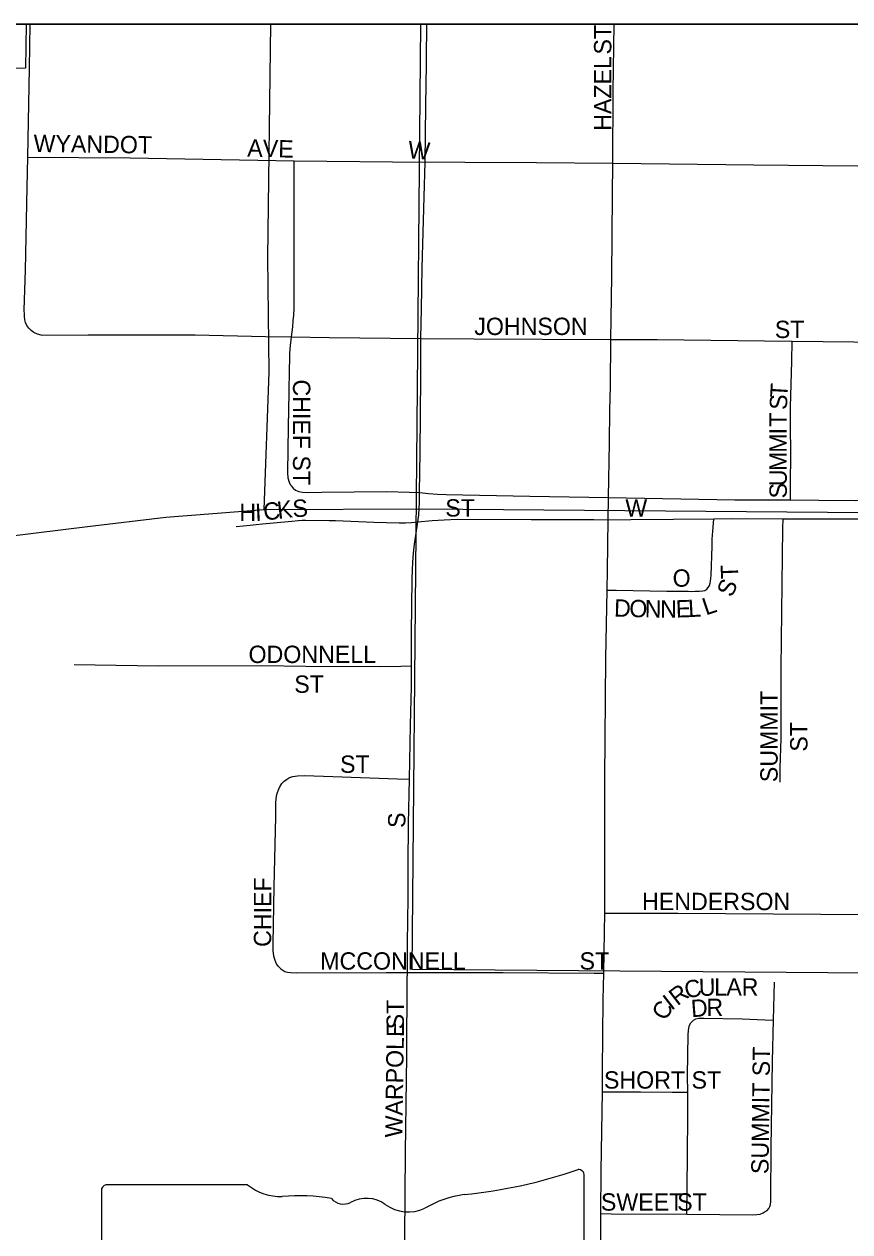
# Model space of a CAD drawing. Extents: x -17 to 88, y -5 to 22.
# Drawn here: x 3.207 to 3.658, y 20.24 to 20.9 of the extents above; entities that cross this region are included whole.
import ezdxf

# ---------------------------------------------------------------- set-up
doc = ezdxf.new("R2010")
doc.units = 0
for name, color, linetype in [('GM_X_City_Street', 7, 'Continuous'), ('GM_X_City_Street_Text', 7, 'Continuous'), ('GM_X_Corporation', 7, 'Continuous'), ('GM_X_Rail_Line', 7, 'Continuous'), ('GM_X_Section', 7, 'Continuous'), ('GM_X_State_Route', 7, 'Continuous'), ('GM_X_State_Shield', 7, 'Continuous'), ('GM_X_Township', 7, 'Continuous'), ('SH_Data', 7, 'Continuous')]:
    doc.layers.add(name, color=color, linetype=linetype)

msp = doc.modelspace()

# ---------------------------------------------------------------- linework, layer by layer
at = {"layer": 'GM_X_City_Street'}
for points in [[(3.20976, 20.876), (3.2101, 20.9)], [(3.52839, 20.82388), (3.52853, 20.86326), (3.52903, 20.9)], [(3.20868, 20.8274), (3.20976, 20.876)], [(3.21609, 20.73019), (3.214, 20.73059), (3.2121, 20.73148), (3.2106, 20.73258), (3.2093, 20.73388), (3.2083, 20.73547), (3.20751, 20.73697), (3.20716, 20.73856), (3.20692, 20.74025), (3.20694, 20.74145), (3.20683, 20.74388), (3.20755, 20.76561), (3.20835, 20.81102), (3.20868, 20.8274)], [(3.20868, 20.8274), (3.26459, 20.82697), (3.35427, 20.82531)], [(3.35288, 20.72913), (3.35351, 20.73469), (3.35379, 20.73793), (3.35407, 20.74103), (3.35425, 20.74477), (3.35424, 20.77965), (3.35424, 20.81582), (3.35427, 20.82531)], [(3.35427, 20.82531), (3.4259, 20.82461)], [(3.4235, 20.72831), (3.42378, 20.74441), (3.42419, 20.76682), (3.42525, 20.8056), (3.4259, 20.82461)], [(3.52718, 20.72779), (3.52776, 20.76221), (3.52814, 20.80701), (3.52839, 20.82388)], [(3.21609, 20.73019), (3.24166, 20.73029), (3.30011, 20.73033), (3.33862, 20.72939), (3.35288, 20.72913)], [(3.35247, 20.64795), (3.35164, 20.6496), (3.35098, 20.65199), (3.35075, 20.65509), (3.35114, 20.67994), (3.35147, 20.69858), (3.35178, 20.71177), (3.3519, 20.71669), (3.35198, 20.72026), (3.35231, 20.72442), (3.35288, 20.72913)], [(3.35288, 20.72913), (3.37341, 20.72875), (3.4235, 20.72831)], [(3.4228, 20.64416), (3.42302, 20.66621), (3.4235, 20.70733), (3.4235, 20.72831)], [(3.4235, 20.72831), (3.45249, 20.72806), (3.52718, 20.72779)], [(3.52605, 20.64136), (3.52658, 20.67127), (3.52671, 20.68912), (3.52705, 20.70212), (3.52718, 20.72779)], [(3.52718, 20.72779), (3.55257, 20.7277), (3.6259, 20.72681), (3.62637, 20.72681)], [(3.62542, 20.6402), (3.62545, 20.64614), (3.62557, 20.66775), (3.62543, 20.67838), (3.62532, 20.69076), (3.62605, 20.71585), (3.62637, 20.72681)], [(3.62637, 20.72681), (3.67687, 20.72619), (3.71749, 20.72582)], [(3.35247, 20.64795), (3.35372, 20.64648), (3.35498, 20.64548), (3.35674, 20.64472), (3.35889, 20.64434), (3.36127, 20.64423), (3.36933, 20.6443), (3.40471, 20.64463), (3.41721, 20.64442), (3.4228, 20.64416)], [(3.42184, 20.6281), (3.42237, 20.63198), (3.42263, 20.63534), (3.42273, 20.63864), (3.4228, 20.64416)], [(3.4228, 20.64416), (3.42772, 20.64369), (3.43248, 20.64328), (3.43733, 20.64303), (3.48292, 20.64211), (3.52605, 20.64136)], [(3.62542, 20.6402), (3.6409, 20.64002), (3.66078, 20.63987), (3.67505, 20.64021), (3.68133, 20.64041), (3.68742, 20.64081), (3.6923, 20.64116), (3.69797, 20.6418), (3.70327, 20.64231), (3.70958, 20.64307), (3.71672, 20.64412)], [(3.52584, 20.62927), (3.52605, 20.64136)], [(3.52605, 20.64136), (3.59491, 20.64017), (3.62164, 20.64023), (3.62542, 20.6402)], [(3.52528, 20.59086), (3.53024, 20.59078), (3.55778, 20.59028), (3.56954, 20.59019), (3.57143, 20.59014), (3.57339, 20.5902), (3.57561, 20.5902), (3.57743, 20.59037), (3.57861, 20.59071), (3.57965, 20.59134), (3.58048, 20.59224), (3.58106, 20.59333), (3.58154, 20.59464), (3.58172, 20.59572), (3.5819, 20.59745), (3.58203, 20.59881), (3.58256, 20.6149), (3.58269, 20.61845), (3.58279, 20.62108), (3.58293, 20.62294), (3.58311, 20.62523), (3.58347, 20.62982)], [(3.52584, 20.62927), (3.5381, 20.62938), (3.56144, 20.62964), (3.58347, 20.62982)], [(3.58347, 20.62982), (3.59372, 20.62991), (3.62134, 20.62971)], [(3.61977, 20.48595), (3.61981, 20.49375), (3.62023, 20.50981), (3.62031, 20.52217), (3.62031, 20.54139), (3.62035, 20.54815), (3.62127, 20.62474), (3.62134, 20.62971)], [(3.62134, 20.62971), (3.6434, 20.62981), (3.65022, 20.62978), (3.66829, 20.62974), (3.69256, 20.62913), (3.70785, 20.62879), (3.7166, 20.62863)], [(3.32254, 20.62566), (3.33017, 20.62636), (3.33352, 20.62667), (3.33696, 20.62698), (3.35303, 20.62856), (3.35636, 20.62886), (3.3586, 20.62904), (3.36047, 20.62903), (3.37333, 20.62891), (3.37684, 20.62881), (3.39775, 20.62792), (3.41155, 20.62753), (3.41513, 20.62766), (3.41843, 20.62781), (3.42184, 20.6281)], [(3.41834, 20.54943), (3.41844, 20.56743), (3.41869, 20.59689), (3.41885, 20.60168), (3.41903, 20.60619), (3.4194, 20.611), (3.42002, 20.61593), (3.42073, 20.62074), (3.42184, 20.6281)], [(3.42184, 20.6281), (3.42961, 20.6288), (3.43611, 20.62928), (3.44331, 20.62952), (3.48373, 20.62941), (3.49681, 20.62943), (3.51803, 20.62932), (3.52584, 20.62927)], [(3.52528, 20.59086), (3.52534, 20.60168), (3.52584, 20.62927)], [(3.52389, 20.41445), (3.5239, 20.42282), (3.52394, 20.45876), (3.52397, 20.48768), (3.52453, 20.55361), (3.52528, 20.59086)], [(3.2341, 20.55019), (3.28003, 20.54939), (3.33647, 20.54966), (3.36061, 20.54929), (3.40157, 20.54913), (3.4125, 20.54932), (3.41834, 20.54943)], [(3.4172, 20.48747), (3.41787, 20.51714), (3.41828, 20.53826), (3.41834, 20.54943)], [(3.34696, 20.38395), (3.34561, 20.38523), (3.34456, 20.38676), (3.34381, 20.38846), (3.34318, 20.39085), (3.34286, 20.39392), (3.34278, 20.39764), (3.34337, 20.4287), (3.3442, 20.46717), (3.34425, 20.47465), (3.34465, 20.4784), (3.34509, 20.48021), (3.34561, 20.48174), (3.34616, 20.48309), (3.34747, 20.48518), (3.34878, 20.48649), (3.35002, 20.48745), (3.35167, 20.48841), (3.35346, 20.48903), (3.35612, 20.48936), (3.35987, 20.4895), (3.37538, 20.48905), (3.41071, 20.48772), (3.4172, 20.48747)], [(3.41608, 20.38188), (3.41622, 20.39796), (3.41651, 20.42278), (3.4165, 20.44078), (3.41665, 20.46315), (3.4172, 20.48747)], [(3.52335, 20.38163), (3.52384, 20.40419), (3.52389, 20.41445)], [(3.52389, 20.41445), (3.56376, 20.41436), (3.64204, 20.41384), (3.70612, 20.4133), (3.71541, 20.41323)], [(3.34696, 20.38395), (3.34799, 20.38317), (3.34909, 20.38254), (3.35053, 20.3822), (3.35231, 20.38194), (3.35541, 20.38178), (3.40458, 20.38187), (3.41608, 20.38188)], [(3.41439, 20.17199), (3.4143, 20.19314), (3.41465, 20.23713), (3.41516, 20.28354), (3.41574, 20.33647), (3.41605, 20.37809), (3.41608, 20.38188)], [(3.41608, 20.38188), (3.46843, 20.38192), (3.51817, 20.38166), (3.52335, 20.38163)], [(3.52262, 20.31682), (3.52274, 20.32839), (3.52303, 20.36695), (3.52335, 20.38163)], [(3.61614, 20.35592), (3.61666, 20.3767)], [(3.56923, 20.31662), (3.56916, 20.3256), (3.56956, 20.34793), (3.56971, 20.3502), (3.5698, 20.35156), (3.57019, 20.35318), (3.57086, 20.35451), (3.5716, 20.35527), (3.57246, 20.35588), (3.57376, 20.35656), (3.57535, 20.35693), (3.57804, 20.35708), (3.59908, 20.35656), (3.61137, 20.35611), (3.61614, 20.35592)], [(3.6126, 20.25197), (3.61354, 20.25309), (3.61416, 20.25412), (3.61443, 20.25521), (3.6147, 20.25693), (3.61474, 20.25894), (3.61485, 20.28616), (3.61559, 20.33332), (3.61614, 20.35592)], [(3.52175, 20.25023), (3.52188, 20.27363), (3.52262, 20.31682)], [(3.52262, 20.31682), (3.52807, 20.31681), (3.54348, 20.3167), (3.56071, 20.31665), (3.56923, 20.31662)], [(3.56882, 20.24992), (3.56895, 20.26356), (3.56935, 20.30267), (3.56923, 20.31662)], [(3.51873, 20.17193), (3.51972, 20.17424), (3.52013, 20.17558), (3.52046, 20.17726), (3.5207, 20.17933), (3.52154, 20.21604), (3.52175, 20.25023)], [(3.52175, 20.25023), (3.52764, 20.25019), (3.56882, 20.24992)], [(3.56882, 20.24992), (3.60473, 20.24961), (3.60697, 20.24973), (3.60875, 20.25001), (3.61039, 20.25062), (3.61163, 20.25131), (3.6126, 20.25197)]]:
    msp.add_lwpolyline(points, dxfattribs=at)
at = {"layer": 'GM_X_Corporation'}
msp.add_line((5.58768, 20.9), (3.20786, 20.9), dxfattribs=at)
msp.add_lwpolyline([(3.20786, 20.9), (3.20744, 20.87591), (2.97062, 20.87171), (2.9713, 20.9)], dxfattribs=at)
at = {"layer": 'GM_X_Rail_Line'}
for points in [[(3.33784, 20.63494), (3.34058, 20.70998), (3.33987, 20.77252), (3.34147, 20.9)], [(2.6, 20.54649), (2.87685, 20.5807), (3.11286, 20.60973), (3.24134, 20.62553), (3.28411, 20.63068), (3.33784, 20.63494)], [(3.33784, 20.63494), (3.42428, 20.63515), (3.66767, 20.63326), (4.04986, 20.62913), (4.41143, 20.62553), (4.69708, 20.62244), (4.78173, 20.62035), (4.83124, 20.61775), (4.87795, 20.61471), (5.02378, 20.6032), (5.35564, 20.57743), (5.53204, 20.56318), (5.63047, 20.55545), (5.71669, 20.54875), (6.32595, 20.50065), (6.53551, 20.48433), (6.65266, 20.47472), (6.95205, 20.45153), (7.27068, 20.42662), (7.45962, 20.41202), (8.17109, 20.35637), (8.73122, 20.31274), (9.05827, 20.28714), (9.4, 20.26034)]]:
    msp.add_lwpolyline(points, dxfattribs=at)
at = {"layer": 'GM_X_Section'}
msp.add_line((3.42344, 20.9), (2.68666, 20.9), dxfattribs=at)
msp.add_lwpolyline([(2.68666, 20.9), (2.68345, 20.1757), (3.71204, 20.17028), (3.71394, 20.3813), (3.41881, 20.38356), (3.42344, 20.9)], dxfattribs=at)
at = {"layer": 'GM_X_State_Route'}
for points in [[(3.4259, 20.82461), (3.42627, 20.8553), (3.42662, 20.87825), (3.42655, 20.88698), (3.42668, 20.8938), (3.42676, 20.9)], [(3.71903, 20.82161), (3.66193, 20.82246), (3.60534, 20.82288), (3.55935, 20.82357), (3.52839, 20.82388), (3.48662, 20.82431), (3.44748, 20.82449), (3.4259, 20.82461)]]:
    msp.add_lwpolyline(points, dxfattribs=at)
at = {"layer": 'GM_X_State_Shield'}
for p, q in [((3.51265, 20.16622), (3.51265, 20.27091)), ((3.24899, 20.2625), (3.24899, 20.06238)), ((3.3288, 20.26595), (3.25158, 20.26595))]:
    msp.add_line(p, q, dxfattribs=at)
for centre, radius, start, end in [((3.41873, 20.53878), 0.27962, 275.84447, 288.90645), ((3.50973, 20.27134), 0.00294, 351.86209, 97.738), ((3.25201, 20.26293), 0.00305, 98.1301, 188.1301), ((3.34719, 20.28918), 0.02963, 231.61951, 271.11188), ((3.4544, 20.20482), 0.05625, 97.34618, 120.76885), ((3.35701, 20.1536), 0.10636, 80.48669, 94.98827), ((3.38116, 20.26397), 0.00855, 219.79206, 297.10237), ((3.39371, 20.24084), 0.01777, 54.46668, 119.14113), ((3.41664, 20.27256), 0.02138, 233.85621, 294.82819)]:
    msp.add_arc(centre, radius, start, end, dxfattribs=at)
at = {"layer": 'GM_X_Township'}
msp.add_line((7.72185, 20.9), (2.68822, 20.9), dxfattribs=at)
at = {"layer": 'SH_Data'}
msp.add_line((2.6, 20.9), (9.4, 20.9), dxfattribs=at)

# ---------------------------------------------------------------- texts
at = {"layer": 'GM_X_City_Street_Text'}
for s, rotation, p in [('ST', 90, (3.52754, 20.88341)), ('HAZEL', 90, (3.52754, 20.84174)), ('WYANDOT', 359.20166, (3.21185, 20.83019)), ('AVE', 358.53134, (3.32856, 20.82769)), ('W', 355.23937, (3.41614, 20.82685)), ('JOHNSON', 0.00001, (3.45266, 20.73019)), ('ST', 0.00001, (3.61683, 20.72852)), ('CHIEF ST', 270, (3.35361, 20.70591)), ('T', 86.50036, (3.62368, 20.69575)), ('S', 87.73231, (3.62342, 20.68914)), ('T', 89.97267, (3.62338, 20.68008)), ('I', 89.98499, (3.62338, 20.67591)), ('M', 89.98178, (3.62338, 20.66591)), ('M', 89.98178, (3.62338, 20.65591)), ('U', 89.99284, (3.62338, 20.64758)), ('S', 89.97267, (3.62337, 20.64091)), ('H', 0.17488, (3.32433, 20.62853)), ('I', 2.78743, (3.33313, 20.62856)), ('C', 6.41159, (3.33795, 20.62882)), ('K', 6.81399, (3.34548, 20.62966)), ('S', 3.0889, (3.35358, 20.63064)), ('ST', 0.00001, (3.43682, 20.63102)), ('W', 0.00001, (3.53516, 20.63102)), ('T', 92.34036, (3.59696, 20.59714)), ('O', 0.00001, (3.56099, 20.59269)), ('S', 66.3911, (3.59343, 20.58646)), ('D', 358.3166, (3.5289, 20.57641)), ('O', 358.38268, (3.53723, 20.57616)), ('N', 359.04692, (3.54569, 20.57593)), ('N', 0.10537, (3.55421, 20.57578)), ('E', 2.00218, (3.56288, 20.57581)), ('L', 3.07958, (3.56974, 20.57605)), ('L', 18.6643, (3.57916, 20.57693)), ('ODONNELL', 0.00001, (3.32933, 20.55102)), ('ST', 0.00001, (3.35432, 20.53473)), ('SUMMIT', 90, (3.61837, 20.48591)), ('ST', 90, (3.63467, 20.50258)), ('ST', 0.00001, (3.37932, 20.49102)), ('S', 90, (3.41504, 20.46091)), ('CHIEF', 90, (3.34171, 20.39591)), ('HENDERSON', 0.00001, (3.54432, 20.41602)), ('MCCONNELL', 0.00001, (3.36849, 20.38352)), ('ST', 0.00001, (3.51016, 20.38352)), ('R', 37.57895, (3.56363, 20.36342)), ('C', 12.43398, (3.56858, 20.36754)), ('U', 1.85818, (3.57545, 20.36909)), ('L', 0.00001, (3.5837, 20.36936)), ('A', 0.00001, (3.59036, 20.36936)), ('R', 0.00001, (3.5987, 20.36936)), ('ST', 90, (3.41421, 20.35091)), ('C', 60.3274, (3.55726, 20.35511)), ('I', 37.6219, (3.56033, 20.36088)), ('D', 4.52947, (3.57138, 20.35747)), ('R', 0.82574, (3.57953, 20.35812)), ('WARPOLE', 89.14533, (3.41338, 20.29177)), ('SUMMIT ST', 89.23652, (3.61337, 20.27177)), ('SHORT ST', 0.00001, (3.52349, 20.31852)), ('SWEET', 0.00001, (3.52182, 20.25186)), ('ST', 0.00001, (3.56349, 20.25186))]:
    msp.add_text(s, height=0.00947, rotation=rotation, dxfattribs=at).set_placement(p)

doc.saveas('drawing.dxf')
